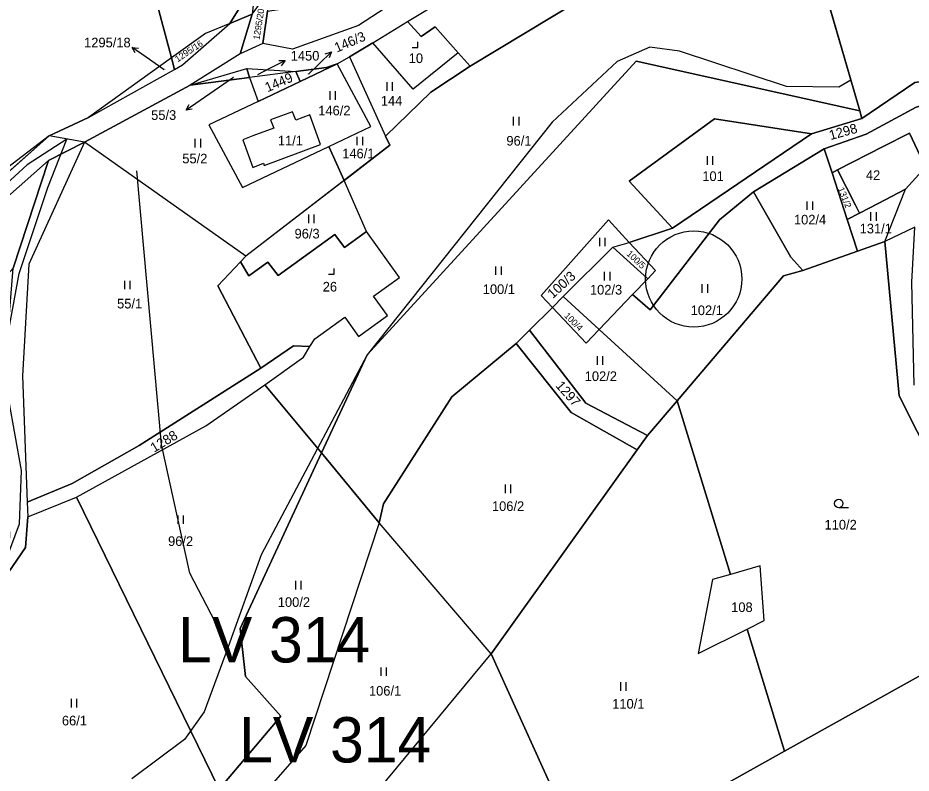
# Model space of a CAD drawing. Extents: x -588699 to -585793, y -1060280 to -1056731.
# Drawn here: x -588200.6 to -588042.9, y -1058381.5 to -1058248.3 of the extents above; entities that cross this region are included whole.
import ezdxf

# ---------------------------------------------------------------- set-up
doc = ezdxf.new("R2010")
doc.units = 0
for name, color, linetype in [('Druh pozemku', 7, 'Continuous'), ('Lesy', 7, 'Continuous'), ('Parcela nároku', 7, 'Continuous'), ('Parcelní číslo', 7, 'Continuous'), ('Vnitřní obvod', 7, 'Continuous'), ('Vnější obvod_k šeření', 7, 'Continuous'), ('Vnější obvod_převzatý', 7, 'Continuous'), ('Změna katastrální hranice', 7, 'Continuous')]:
    doc.layers.add(name, color=color, linetype=linetype)

msp = doc.modelspace()

# ---------------------------------------------------------------- linework, layer by layer
at = {"layer": 'Druh pozemku'}
for p, q in [((-588135.49, -1058259.71), (-588135.49, -1058261.21)), ((-588134.46, -1058261.21), (-588134.46, -1058259.71)), ((-588145.54, -1058261.28), (-588145.54, -1058262.78)), ((-588144.52, -1058262.78), (-588144.52, -1058261.28)), ((-588113.14, -1058265.8), (-588113.14, -1058267.3)), ((-588112.11, -1058267.3), (-588112.11, -1058265.8)), ((-588169.34, -1058269.69), (-588169.34, -1058271.19)), ((-588168.32, -1058271.19), (-588168.32, -1058269.69)), ((-588140.74, -1058269.32), (-588140.74, -1058270.82)), ((-588139.71, -1058270.82), (-588139.71, -1058269.32)), ((-588078.93, -1058272.74), (-588078.93, -1058274.24)), ((-588077.91, -1058274.24), (-588077.91, -1058272.74)), ((-588061.31, -1058280.71), (-588061.31, -1058282.21)), ((-588060.29, -1058282.21), (-588060.29, -1058280.71)), ((-588149.31, -1058283.03), (-588149.31, -1058284.53)), ((-588148.29, -1058284.53), (-588148.29, -1058283.03)), ((-588050.06, -1058282.63), (-588050.06, -1058284.13)), ((-588049.04, -1058284.13), (-588049.04, -1058282.63)), ((-588097.92, -1058287.12), (-588097.92, -1058288.62)), ((-588096.9, -1058288.62), (-588096.9, -1058287.12)), ((-588116.27, -1058292.17), (-588116.27, -1058293.67)), ((-588115.24, -1058293.67), (-588115.24, -1058292.17)), ((-588097.08, -1058293.14), (-588097.08, -1058294.64)), ((-588096.06, -1058294.64), (-588096.06, -1058293.14)), ((-588181.78, -1058294.71), (-588181.78, -1058296.21)), ((-588180.76, -1058296.21), (-588180.76, -1058294.71)), ((-588079.85, -1058295.31), (-588079.85, -1058296.81)), ((-588078.83, -1058296.81), (-588078.83, -1058295.31)), ((-588098.35, -1058308.02), (-588098.35, -1058309.52)), ((-588097.33, -1058309.52), (-588097.33, -1058308.02)), ((-588114.59, -1058330.67), (-588114.59, -1058332.17)), ((-588113.57, -1058332.17), (-588113.57, -1058330.67)), ((-588053.95, -1058334.75), (-588055.7, -1058334.75)), ((-588172.37, -1058336.1), (-588172.37, -1058337.6)), ((-588171.34, -1058337.6), (-588171.34, -1058336.1)), ((-588151.58, -1058347.65), (-588151.58, -1058349.15)), ((-588150.56, -1058349.15), (-588150.56, -1058347.65)), ((-588136.54, -1058362.9), (-588136.54, -1058364.4)), ((-588135.52, -1058364.4), (-588135.52, -1058362.9)), ((-588094.21, -1058365.52), (-588094.21, -1058367.02)), ((-588093.19, -1058367.02), (-588093.19, -1058365.52)), ((-588191.21, -1058368.46), (-588191.21, -1058369.96)), ((-588190.19, -1058369.96), (-588190.19, -1058368.46))]:
    msp.add_line(p, q, dxfattribs=at)
for points in [[(-588131.01, -1058253.56), (-588130.01, -1058253.56), (-588130.01, -1058252.56)], [(-588145.78, -1058293.57), (-588144.78, -1058293.57), (-588144.78, -1058292.57)]]:
    msp.add_lwpolyline(points, dxfattribs=at)
msp.add_circle((-588055.7, -1058334), 0.75, dxfattribs=at)
at = {"layer": 'Lesy'}
for p, q in [((-588092.05, -1058239.54), (-588120.78, -1058256.86)), ((-588051.99, -1058264.75), (-588058.21, -1058243.22)), ((-588120.78, -1058256.86), (-588127.72, -1058261.45)), ((-588042.29, -1058259.76), (-588051.6, -1058266.1)), ((-588127.72, -1058261.45), (-588135.69, -1058269.22)), ((-588051.6, -1058266.1), (-588051.99, -1058264.75)), ((-588195.07, -1058269.17), (-588231.71, -1058301.52)), ((-588188.82, -1058270.29), (-588195.07, -1058269.17)), ((-588135.69, -1058269.22), (-588134.96, -1058270.82)), ((-588160.37, -1058290.37), (-588188.82, -1058270.29)), ((-588134.96, -1058270.82), (-588160.37, -1058290.37))]:
    msp.add_line(p, q, dxfattribs=at)
msp.add_lwpolyline([(-588042.39, -1058313.12), (-588042.77, -1058294.96), (-588042.26, -1058285.27), (-588047.55, -1058287.8), (-588062.03, -1058292.92), (-588064.18, -1058290.52), (-588070.77, -1058279.03), (-588058.25, -1058271.46), (-588050.83, -1058268.88), (-588042, -1058264.1), (-588037.6, -1058262.86), (-588028.63, -1058260.57), (-588026.72, -1058262.49), (-588019.94, -1058256.55), (-588042.29, -1058259.76)], dxfattribs=at)
at = {"layer": 'Parcela nároku'}
for points in [[(-588233.5, -1058111.89), (-588220.72, -1058126.38), (-588187, -1058161.78), (-588186.48, -1058166.56), (-588187.86, -1058166.8), (-588187.14, -1058173.38), (-588195.16, -1058174.34), (-588173.47, -1058255.38), (-588188.13, -1058265.89), (-588195.07, -1058269.17), (-588225.24, -1058292.17), (-588257.55, -1058129.34), (-588255.46, -1058125.26)], [(-588263.75, -1058141.47), (-588276.82, -1058139.7), (-588282.59, -1058193.58), (-588258.92, -1058266.64), (-588254.7, -1058264.42), (-588245.73, -1058275.6), (-588239.91, -1058281.73), (-588239.76, -1058291.89), (-588233.93, -1058298.79), (-588231.71, -1058301.52), (-588195.07, -1058269.17), (-588225.24, -1058292.17), (-588257.55, -1058129.34)], [(-588180.1, -1058228.59), (-588170.87, -1058227.65), (-588170.56, -1058230.7), (-588162.79, -1058229.9), (-588162.42, -1058234.46), (-588155.71, -1058233.81), (-588157.93, -1058236.15), (-588158.6, -1058241.95), (-588163.19, -1058249.31), (-588167.5, -1058251.1), (-588173.47, -1058255.38), (-588195.16, -1058174.34), (-588187.14, -1058173.38), (-588187.86, -1058166.8), (-588186.48, -1058166.56), (-588187, -1058161.78), (-588151.89, -1058174.08), (-588149.31, -1058192.11), (-588168.34, -1058193.67), (-588167.64, -1058200.58), (-588172.15, -1058214.97), (-588181.43, -1058215.92)], [(-588032.03, -1058217.82), (-588032.79, -1058215.62), (-588036.77, -1058216.58), (-588036.38, -1058218.14), (-588035.49, -1058221.71), (-588032.53, -1058220.95), (-588029.94, -1058231.14), (-588028.28, -1058237.68), (-588038.53, -1058241.64), (-588042.41, -1058243.13), (-588043.06, -1058238.01), (-588055.57, -1058242.31), (-588058.21, -1058243.22), (-588051.99, -1058264.75), (-588051.6, -1058266.1), (-588042.29, -1058259.76), (-588019.94, -1058256.55), (-588010.93, -1058249.05), (-588005.9, -1058234.96), (-588005.42, -1058222.88), (-588013.42, -1058225.65), (-588027.07, -1058229.5), (-588029.61, -1058220.15), (-588031.08, -1058220.59)], [(-588065.07, -1058219.48), (-588063.29, -1058225.64), (-588092.05, -1058239.54), (-588120.78, -1058256.86), (-588122.86, -1058254.52), (-588126.94, -1058249.92), (-588129.42, -1058251.63), (-588131.81, -1058249.01), (-588111.87, -1058236.93), (-588079.08, -1058222.84), (-588068.21, -1058220.23)], [(-588142.99, -1058277), (-588134.96, -1058270.82), (-588135.69, -1058269.22), (-588127.72, -1058261.45), (-588120.78, -1058256.86), (-588092.05, -1058239.54), (-588063.29, -1058225.64), (-588061.07, -1058233.32), (-588058.21, -1058243.22), (-588051.99, -1058264.75), (-588091.44, -1058255.97), (-588138.95, -1058307.8), (-588146.99, -1058325.07), (-588157.01, -1058313.06), (-588150.15, -1058308.19), (-588149.06, -1058306.32), (-588148.16, -1058304.94), (-588142.9, -1058301.14), (-588140.46, -1058304.51), (-588135.34, -1058300.83), (-588137.79, -1058297.45), (-588133.2, -1058294.13), (-588139.05, -1058286.04)], [(-588157.37, -1058252.85), (-588156.55, -1058247.18), (-588145.64, -1058245.51), (-588134.5, -1058237.4), (-588128.29, -1058234.64), (-588122.82, -1058232.88), (-588120.43, -1058232.13), (-588122.62, -1058238.02), (-588140.45, -1058249.69), (-588152.13, -1058253.84)], [(-588163.19, -1058249.31), (-588158.6, -1058241.95), (-588159.26, -1058247.68)], [(-588159.26, -1058247.68), (-588155.97, -1058243.19), (-588156.55, -1058247.18), (-588157.37, -1058252.85), (-588161.37, -1058254.66)], [(-588163.19, -1058249.31), (-588159.26, -1058247.68), (-588161.37, -1058254.66), (-588170.17, -1058260.23), (-588188.82, -1058270.29), (-588195.18, -1058273.49), (-588236.69, -1058310.21), (-588240.57, -1058313.64), (-588267.55, -1058333.34), (-588279.64, -1058340.05), (-588283.85, -1058339.62), (-588270.15, -1058331.48), (-588250.18, -1058316.69), (-588246.95, -1058314.3), (-588231.71, -1058301.52), (-588195.07, -1058269.17), (-588188.13, -1058265.89), (-588172.92, -1058257.42), (-588171.55, -1058256.65)], [(-588167.5, -1058251.1), (-588173.47, -1058255.38), (-588172.92, -1058257.42), (-588171.55, -1058256.65), (-588163.19, -1058249.31)], [(-588137.93, -1058252.72), (-588131.81, -1058249.01), (-588129.42, -1058251.63), (-588126.94, -1058249.92), (-588122.86, -1058254.52), (-588130.8, -1058260.9)], [(-588122.86, -1058254.52), (-588130.8, -1058260.9), (-588137.93, -1058252.72), (-588142.05, -1058255.22), (-588135.69, -1058269.22), (-588127.72, -1058261.45), (-588120.78, -1058256.86)], [(-588173.47, -1058255.38), (-588188.13, -1058265.89), (-588172.92, -1058257.42)], [(-588150.78, -1058259.54), (-588158.2, -1058263.08), (-588166.91, -1058267.23), (-588160.93, -1058278.28), (-588145.68, -1058271.02), (-588138.3, -1058267.51), (-588144.26, -1058256.44)], [(-588146.11, -1058257.12), (-588151.54, -1058257.82), (-588150.78, -1058259.54), (-588144.26, -1058256.44)], [(-588108.25, -1058297.31), (-588106.25, -1058299.42), (-588110.31, -1058303.45), (-588112.61, -1058305.76), (-588123.98, -1058315.18), (-588136.08, -1058334.04), (-588136.79, -1058337.39), (-588146.99, -1058325.07), (-588138.95, -1058307.8), (-588091.44, -1058255.97), (-588051.99, -1058264.75), (-588051.6, -1058266.1), (-588060.5, -1058268.79), (-588077.62, -1058266.16), (-588092.68, -1058277.16), (-588085.06, -1058285.41), (-588092.66, -1058287.94), (-588096.34, -1058283.98)], [(-588145.68, -1058271.02), (-588138.3, -1058267.51), (-588144.26, -1058256.44), (-588142.05, -1058255.22), (-588135.69, -1058269.22), (-588134.96, -1058270.82), (-588142.99, -1058277)], [(-588092.09, -1058297.15), (-588089.42, -1058294.34), (-588088.04, -1058292.89), (-588092.66, -1058287.94), (-588085.06, -1058285.41), (-588060.5, -1058268.79), (-588051.6, -1058266.1), (-588042.29, -1058259.76), (-588019.94, -1058256.55), (-588026.72, -1058262.49), (-588028.63, -1058260.57), (-588037.6, -1058262.86), (-588042, -1058264.1), (-588050.83, -1058268.88), (-588058.25, -1058271.46), (-588070.77, -1058279.03), (-588076.72, -1058283.98), (-588088.99, -1058299.83)], [(-588170.17, -1058260.23), (-588160.2, -1058257.29), (-588159.68, -1058258.87)], [(-588160.2, -1058257.29), (-588151.54, -1058257.82), (-588159.68, -1058258.87)], [(-588150.78, -1058259.54), (-588151.54, -1058257.82), (-588159.68, -1058258.87), (-588158.2, -1058263.08)], [(-588166.91, -1058267.23), (-588160.93, -1058278.28), (-588145.68, -1058271.02), (-588142.99, -1058277), (-588160.37, -1058290.37), (-588188.82, -1058270.29), (-588170.17, -1058260.23), (-588159.68, -1058258.87), (-588158.2, -1058263.08)], [(-588050.83, -1058268.88), (-588058.25, -1058271.46), (-588056.88, -1058275.65), (-588055.94, -1058275.17), (-588047.85, -1058271.04), (-588043.18, -1058268.66), (-588040.35, -1058274.68), (-588035.53, -1058269.41), (-588037.6, -1058262.86), (-588042, -1058264.1)], [(-588155.42, -1058267.81), (-588159.09, -1058269.16), (-588160.91, -1058269.84), (-588159.13, -1058274.73), (-588157.25, -1058273.96), (-588157.09, -1058274.36), (-588147.17, -1058270.66), (-588149.03, -1058265.45), (-588151.55, -1058266.38), (-588152.09, -1058264.9), (-588155.98, -1058266.3)], [(-588155.98, -1058266.3), (-588155.42, -1058267.81), (-588159.09, -1058269.16), (-588160.91, -1058269.84), (-588159.13, -1058274.73), (-588157.25, -1058273.96), (-588157.09, -1058274.36), (-588147.17, -1058270.66), (-588149.03, -1058265.45), (-588151.55, -1058266.38), (-588152.09, -1058264.9)], [(-588092.68, -1058277.16), (-588077.62, -1058266.16), (-588060.5, -1058268.79), (-588085.06, -1058285.41)], [(-588040.35, -1058274.68), (-588043.18, -1058268.66), (-588047.85, -1058271.04), (-588055.94, -1058275.17), (-588052.74, -1058281.38), (-588052.03, -1058282.76), (-588048.73, -1058281.06), (-588043.9, -1058278.57)], [(-588283.37, -1058455.17), (-588274.9, -1058429.78), (-588264.76, -1058419.13), (-588236.43, -1058389.38), (-588229.89, -1058381.41), (-588202.03, -1058340), (-588202.09, -1058337.86), (-588202.2, -1058334.18), (-588202.91, -1058310.84), (-588201.43, -1058292.5), (-588195.18, -1058273.49), (-588188.82, -1058270.29), (-588198.66, -1058291.81), (-588199.76, -1058311.5), (-588198.93, -1058333.77), (-588198.84, -1058336.33), (-588199.24, -1058341.78), (-588231.84, -1058389.25), (-588271.28, -1058432.34), (-588280.04, -1058457.03), (-588290.75, -1058481.45), (-588298.28, -1058488.56), (-588287.12, -1058463.52)], [(-588198.66, -1058291.81), (-588199.76, -1058311.5), (-588198.93, -1058333.77), (-588190.99, -1058330.44), (-588179.16, -1058323.79), (-588157.73, -1058310.11), (-588165.3, -1058295.6), (-588161.32, -1058291.37), (-588160.37, -1058290.37), (-588188.82, -1058270.29)], [(-588070.77, -1058279.03), (-588064.18, -1058290.52), (-588062.03, -1058292.92), (-588052.36, -1058289.5), (-588054.2, -1058283.88), (-588056.88, -1058275.65), (-588058.25, -1058271.46)], [(-588236.69, -1058310.21), (-588195.18, -1058273.49), (-588201.43, -1058292.5), (-588219.54, -1058312.83)], [(-588052.03, -1058282.76), (-588052.74, -1058281.38), (-588055.94, -1058275.17), (-588056.88, -1058275.65), (-588054.2, -1058283.88)], [(-588142.99, -1058277), (-588160.37, -1058290.37), (-588161.32, -1058291.37), (-588159.83, -1058293.86), (-588156.45, -1058291.4), (-588154.67, -1058293.77), (-588144.63, -1058286.53), (-588142.96, -1058288.85), (-588139.05, -1058286.04)], [(-588043.9, -1058278.57), (-588048.73, -1058281.06), (-588052.03, -1058282.76), (-588054.2, -1058283.88), (-588052.36, -1058289.5), (-588047.55, -1058287.8)], [(-588070.77, -1058279.03), (-588064.18, -1058290.52), (-588062.03, -1058292.92), (-588065.47, -1058293.85), (-588084.22, -1058315.89), (-588097.96, -1058303.31), (-588092.09, -1058297.15), (-588088.99, -1058299.83), (-588076.72, -1058283.98)], [(-588092.66, -1058287.94), (-588096.34, -1058283.98), (-588108.25, -1058297.31), (-588106.25, -1058299.42), (-588104.31, -1058297.49), (-588095.55, -1058288.8)], [(-588139.05, -1058286.04), (-588142.96, -1058288.85), (-588144.63, -1058286.53), (-588154.67, -1058293.77), (-588156.45, -1058291.4), (-588159.83, -1058293.86), (-588161.32, -1058291.37), (-588165.3, -1058295.6), (-588157.73, -1058310.11), (-588151.96, -1058306.2), (-588149.06, -1058306.32), (-588148.16, -1058304.94), (-588142.9, -1058301.14), (-588140.46, -1058304.51), (-588135.34, -1058300.83), (-588137.79, -1058297.45), (-588133.2, -1058294.13)], [(-588092.66, -1058287.94), (-588088.04, -1058292.89), (-588089.42, -1058294.34), (-588095.55, -1058288.8)], [(-588047.55, -1058287.8), (-588045.05, -1058315.03), (-588032.3, -1058340.17), (-588020.5, -1058352.76), (-588065.25, -1058377.7), (-588071.87, -1058356.13), (-588068.84, -1058354.61), (-588069.58, -1058344.99), (-588074.83, -1058346.49), (-588084.22, -1058315.89), (-588065.47, -1058293.85), (-588062.03, -1058292.92), (-588052.36, -1058289.5)], [(-588104.31, -1058297.49), (-588095.55, -1058288.8), (-588089.42, -1058294.34), (-588092.09, -1058297.15), (-588097.96, -1058303.31)], [(-588106.25, -1058299.42), (-588104.31, -1058297.49), (-588097.96, -1058303.31), (-588100.26, -1058305.73)], [(-588110.31, -1058303.45), (-588106.25, -1058299.42), (-588100.26, -1058305.73), (-588097.96, -1058303.31), (-588084.22, -1058315.89), (-588089.43, -1058322.02), (-588100.33, -1058316.29)], [(-588112.61, -1058305.76), (-588110.31, -1058303.45), (-588100.33, -1058316.29), (-588089.43, -1058322.02), (-588091.25, -1058324.55), (-588102.91, -1058317.96)], [(-588179.16, -1058323.79), (-588190.99, -1058330.44), (-588198.93, -1058333.77), (-588198.84, -1058336.33), (-588190.26, -1058332.87), (-588167.4, -1058320.3), (-588157.01, -1058313.06), (-588150.15, -1058308.19), (-588149.06, -1058306.32), (-588151.96, -1058306.2), (-588157.73, -1058310.11)], [(-588123.98, -1058315.18), (-588112.61, -1058305.76), (-588102.91, -1058317.96), (-588091.25, -1058324.55), (-588117.02, -1058360.48), (-588136.79, -1058337.39), (-588136.08, -1058334.04)], [(-588161.36, -1058356.04), (-588160.44, -1058364.53), (-588154.15, -1058371.52), (-588165.06, -1058384.36), (-588190.26, -1058332.87), (-588167.4, -1058320.3), (-588157.01, -1058313.06), (-588146.99, -1058325.07)], [(-588080.48, -1058360.43), (-588071.87, -1058356.13), (-588065.25, -1058377.7), (-588101.59, -1058397.94), (-588103.43, -1058390.47), (-588117.02, -1058360.48), (-588091.25, -1058324.55), (-588089.43, -1058322.02), (-588084.22, -1058315.89), (-588074.83, -1058346.49), (-588077.99, -1058347.4)], [(-588165.06, -1058384.36), (-588154.15, -1058371.52), (-588160.44, -1058364.53), (-588161.36, -1058356.04), (-588146.99, -1058325.07), (-588136.79, -1058337.39), (-588149.78, -1058376.65), (-588161.99, -1058390.65)], [(-588199.24, -1058341.78), (-588198.84, -1058336.33), (-588190.26, -1058332.87), (-588165.06, -1058384.36), (-588204.14, -1058407.47), (-588207.77, -1058386.34), (-588227.9, -1058405.85), (-588280.04, -1058457.03), (-588271.28, -1058432.34), (-588231.84, -1058389.25)], [(-588117.02, -1058360.48), (-588136.79, -1058337.39), (-588149.78, -1058376.65), (-588161.99, -1058390.65), (-588149.82, -1058397.49), (-588136.9, -1058384.46)], [(-588068.84, -1058354.61), (-588069.58, -1058344.99), (-588074.83, -1058346.49), (-588077.99, -1058347.4), (-588080.48, -1058360.43), (-588071.87, -1058356.13)], [(-588065.25, -1058377.7), (-588020.5, -1058352.76), (-588017.24, -1058356.23), (-588026.95, -1058382.89), (-588045.14, -1058394.57), (-588097.06, -1058422.02), (-588098.53, -1058410.35), (-588101.59, -1058397.94)], [(-588149.82, -1058397.49), (-588136.9, -1058384.46), (-588117.02, -1058360.48), (-588103.43, -1058390.47), (-588101.59, -1058397.94), (-588098.53, -1058410.35), (-588097.06, -1058422.02), (-588111.41, -1058432.85), (-588120.77, -1058441.9), (-588135.35, -1058457.5), (-588157.66, -1058421), (-588156.72, -1058411.08)]]:
    msp.add_lwpolyline(points, close=True, dxfattribs=at)
for points in [[(-588026.8, -1058194.23), (-588052.9, -1058201.43), (-588052.21, -1058203.52), (-588082.74, -1058217.13), (-588122.62, -1058238.02), (-588140.45, -1058249.69), (-588152.13, -1058253.84), (-588157.37, -1058252.85), (-588161.37, -1058254.66), (-588170.17, -1058260.23), (-588160.2, -1058257.29), (-588151.54, -1058257.82), (-588146.11, -1058257.12), (-588144.26, -1058256.44), (-588142.05, -1058255.22), (-588137.93, -1058252.72), (-588131.81, -1058249.01), (-588111.87, -1058236.93), (-588070.92, -1058215.21), (-588058.38, -1058208.56), (-588048.39, -1058205.39), (-588029.03, -1058199.24)], [(-588032.3, -1058340.17), (-588045.05, -1058315.03), (-588047.55, -1058287.8), (-588043.9, -1058278.57), (-588040.35, -1058274.68)]]:
    msp.add_lwpolyline(points, dxfattribs=at)
at = {"layer": 'Parcelní číslo'}
for p, q in [((-588177.94, -1058255.27), (-588180.39, -1058253.54)), ((-588147.4, -1058256.44), (-588145.26, -1058254.33)), ((-588174.78, -1058257.51), (-588177.94, -1058255.27)), ((-588156.1, -1058257.24), (-588153.43, -1058255.88)), ((-588149.29, -1058258.3), (-588147.4, -1058256.44)), ((-588158.25, -1058258.33), (-588156.1, -1058257.24)), ((-588162.56, -1058258.84), (-588168.44, -1058262.92)), ((-588168.44, -1058262.92), (-588170.91, -1058264.63))]:
    msp.add_line(p, q, dxfattribs=at)
for points in [[(-588179.86, -1058254.52), (-588180.39, -1058253.54), (-588179.28, -1058253.71)], [(-588146.33, -1058254.68), (-588145.26, -1058254.33), (-588145.62, -1058255.39)], [(-588154.54, -1058255.89), (-588153.43, -1058255.88), (-588154.09, -1058256.78)], [(-588169.8, -1058264.47), (-588170.91, -1058264.63), (-588170.37, -1058263.65)]]:
    msp.add_lwpolyline(points, dxfattribs=at)
at = {"layer": 'Vnitřní obvod'}
for points in [[(-588191.94, -1058269.73), (-588198.97, -1058274.28), (-588212.08, -1058286.24), (-588220.48, -1058295.28), (-588225.45, -1058301.27), (-588230.18, -1058305.31), (-588243.74, -1058314.96), (-588258.25, -1058324.96), (-588268.22, -1058332.75), (-588282.52, -1058341.26), (-588286.56, -1058343.66), (-588293.95, -1058345.35), (-588308.3, -1058346.81), (-588315.88, -1058349.9), (-588320.71, -1058351.87), (-588328.74, -1058359.49), (-588342.46, -1058373.88), (-588354.02, -1058383.85), (-588368.24, -1058393.93), (-588378.63, -1058400.49), (-588387.38, -1058405.6), (-588393.78, -1058408.34), (-588411.62, -1058413.95)], [(-588232.82, -1058388.18), (-588224.91, -1058377.38), (-588215.1, -1058363.19), (-588203.84, -1058346.9), (-588200.31, -1058337.56), (-588199.93, -1058328.2), (-588203.28, -1058309.5), (-588200.35, -1058293.4), (-588195.33, -1058278.28), (-588191.94, -1058269.73)]]:
    msp.add_lwpolyline(points, dxfattribs=at)
at = {"layer": 'Vnější obvod_k šeření'}
for points in [[(-588053.56, -1058259.32), (-588055.69, -1058260.55), (-588064.91, -1058260.42), (-588083.8, -1058254.21), (-588089.03, -1058253.49), (-588094.78, -1058256.04), (-588106.29, -1058266.76), (-588138.95, -1058307.8), (-588157.67, -1058343.07), (-588163.49, -1058359.29), (-588167.73, -1058370.73), (-588171.2, -1058375.64), (-588180.48, -1058382.57)], [(-588163.49, -1058359.29), (-588170.21, -1058346.3), (-588175.24, -1058323.61), (-588179.61, -1058275.3)]]:
    msp.add_lwpolyline(points, dxfattribs=at)
at = {"layer": 'Změna katastrální hranice'}
msp.add_circle((-588081.29, -1058294.4), 8.49, dxfattribs=at)

# ---------------------------------------------------------------- texts
at = {"layer": 'Parcela nároku'}
for s, height, rotation, p in [('1295/20', 1.14, 80.9037, (-588157.95, -1058252.27)), ('1295/16', 1.14, 33.6901, (-588172.39, -1058256.2)), ('1449', 1.7, 23.1836, (-588156.53, -1058261.48)), ('1298', 1.7, 15.5333, (-588057.13, -1058269.91)), ('131/2', 1.14, 292.4165, (-588055.89, -1058278.48)), ('100/5', 1.14, 316.6748, (-588093.23, -1058290.09)), ('100/3', 1.7, 42.3574, (-588106.18, -1058297.95)), ('100/4', 1.14, 315, (-588104.24, -1058300.97)), ('1297', 1.7, 311.7965, (-588105.77, -1058313.29)), ('1288', 1.7, 31.0117, (-588176.55, -1058325.05))]:
    msp.add_text(s, height=height, rotation=rotation, dxfattribs=at).set_placement(p)
for s, height, p in [('10', 1.7, (-588131.6, -1058256.31)), ('1295/18', 0.1, (-588175, -1058257.51)), ('1450', 0.1, (-588158.37, -1058258.33)), ('146/3', 0.1, (-588149.45, -1058258.3)), ('55/3', 0.1, (-588162.71, -1058258.84)), ('144', 1.7, (-588136.52, -1058263.81)), ('146/2', 1.7, (-588147.57, -1058265.54)), ('11/1', 1.7, (-588154.7, -1058270.83)), ('96/1', 1.7, (-588114.36, -1058270.87)), ('55/2', 1.7, (-588171.57, -1058274)), ('146/1', 1.7, (-588143.34, -1058273.11)), ('101', 1.7, (-588079.78, -1058277.11)), ('42', 1.7, (-588050.9, -1058276.93)), ('102/4', 1.7, (-588063.6, -1058284.78)), ('131/1', 1.7, (-588052.01, -1058286.36)), ('96/3', 1.7, (-588151.75, -1058287.25)), ('26', 1.7, (-588146.78, -1058296.61)), ('100/1', 1.7, (-588118.53, -1058297.04)), ('102/3', 1.7, (-588099.61, -1058297.14)), ('55/1', 1.7, (-588183.08, -1058299.59)), ('102/1', 1.7, (-588081.83, -1058300.77)), ('102/2', 1.7, (-588100.53, -1058312.39)), ('106/2', 1.7, (-588116.91, -1058335.31)), ('110/2', 1.7, (-588058.2, -1058338.58)), ('96/2', 1.7, (-588174.08, -1058341.48)), ('100/2', 1.7, (-588154.71, -1058352.23)), ('108', 1.7, (-588074.68, -1058353.13)), ('106/1', 1.7, (-588138.62, -1058367.87)), ('110/1', 1.7, (-588095.68, -1058370.17)), ('66/1', 1.7, (-588192.82, -1058373.13))]:
    msp.add_text(s, height=height, dxfattribs=at).set_placement(p)
at = {"layer": 'Parcelní číslo'}
for s, p in [('1295/18', (-588188.9, -1058253.54)), ('1450', (-588152.43, -1058255.88)), ('55/3', (-588177.07, -1058266.33))]:
    msp.add_text(s, height=1.7, dxfattribs=at).set_placement(p)
msp.add_text('146/3', height=1.7, rotation=23.0757, dxfattribs=at).set_placement((-588144.28, -1058254.47))
at = {"layer": 'Vnější obvod_převzatý'}
for p in [(-588172.31, -1058362.02), (-588161.53, -1058379.67)]:
    msp.add_text('LV 314', height=8, dxfattribs=at).set_placement(p)

doc.saveas('drawing.dxf')
